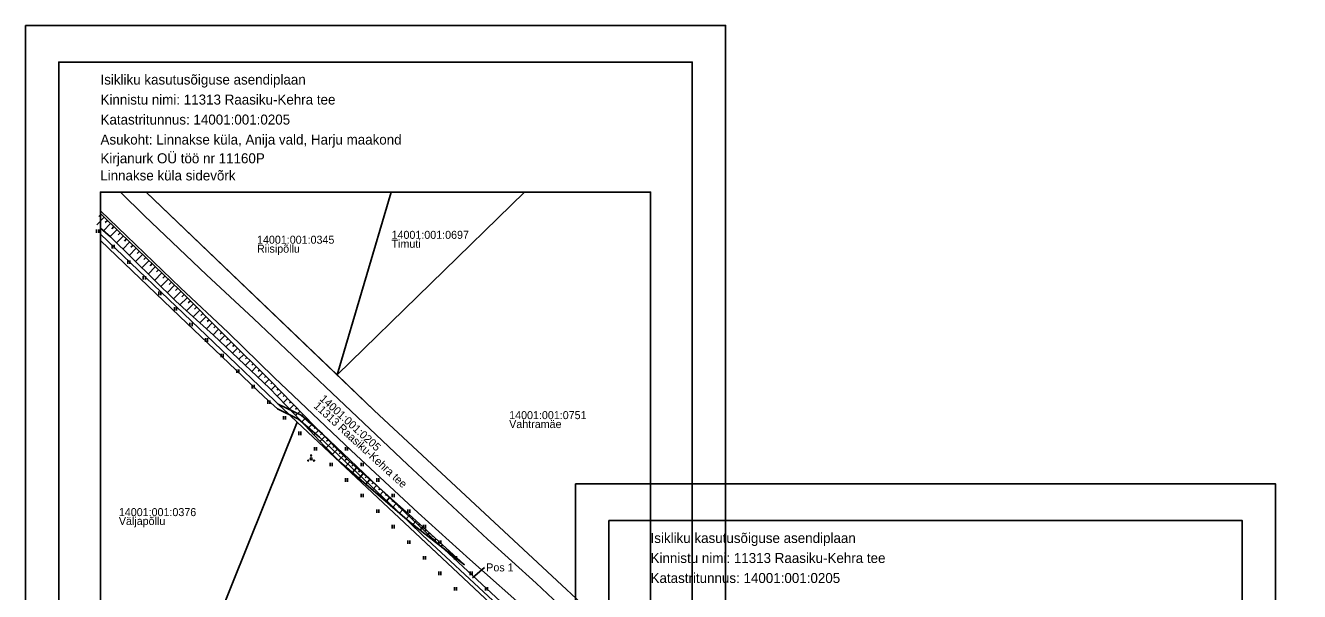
# Model space of a CAD drawing. Extents: x 567864 to 568657, y 6579839 to 6580994.
# Drawn here: x 567863.8 to 568150.4, y 6580866.9 to 6580994.3 of the extents above; entities that cross this region are included whole.
import ezdxf

# ---------------------------------------------------------------- set-up
doc = ezdxf.new("R2010")
doc.units = 0
for name, color, linetype in [('HALJASTUS', 7, 'Continuous'), ('KASUTUSALA', 7, 'Continuous'), ('PIIR', 7, 'Continuous'), ('PR_SIDE', 7, 'Continuous'), ('PUU', 7, 'Continuous'), ('RELJEEF', 7, 'Continuous'), ('TEE', 7, 'Continuous'), ('VORMISTUS', 7, 'Continuous'), ('VORMISTUS_1', 7, 'Continuous')]:
    doc.layers.add(name, color=color, linetype=linetype)

msp = doc.modelspace()

# ---------------------------------------------------------------- linework, layer by layer
at = {"layer": 'HALJASTUS'}
for p, q in [((567879.77, 6580948.38), (567879.77, 6580947.62)), ((567880.23, 6580948.38), (567880.23, 6580947.62)), ((567883.27, 6580944.88), (567883.27, 6580944.12)), ((567883.73, 6580944.88), (567883.73, 6580944.12)), ((567886.77, 6580941.38), (567886.77, 6580940.62)), ((567887.23, 6580941.38), (567887.23, 6580940.62)), ((567890.27, 6580937.88), (567890.27, 6580937.12)), ((567890.73, 6580937.88), (567890.73, 6580937.12)), ((567893.77, 6580934.38), (567893.77, 6580933.62)), ((567894.23, 6580934.38), (567894.23, 6580933.62)), ((567897.27, 6580930.88), (567897.27, 6580930.12)), ((567897.73, 6580930.88), (567897.73, 6580930.12)), ((567900.77, 6580927.38), (567900.77, 6580926.62)), ((567901.23, 6580927.38), (567901.23, 6580926.62)), ((567904.27, 6580923.88), (567904.27, 6580923.12)), ((567904.73, 6580923.88), (567904.73, 6580923.12)), ((567907.77, 6580920.38), (567907.77, 6580919.62)), ((567908.23, 6580920.38), (567908.23, 6580919.62)), ((567911.27, 6580916.88), (567911.27, 6580916.12)), ((567911.73, 6580916.88), (567911.73, 6580916.12)), ((567914.77, 6580913.38), (567914.77, 6580912.62)), ((567915.23, 6580913.38), (567915.23, 6580912.62)), ((567918.27, 6580909.88), (567918.27, 6580909.12)), ((567918.73, 6580909.88), (567918.73, 6580909.12)), ((567921.77, 6580906.38), (567921.77, 6580905.62)), ((567922.23, 6580906.38), (567922.23, 6580905.62)), ((567925.27, 6580902.88), (567925.27, 6580902.12)), ((567925.73, 6580902.88), (567925.73, 6580902.12)), ((567928.77, 6580899.38), (567928.77, 6580898.62)), ((567929.23, 6580899.38), (567929.23, 6580898.62)), ((567935.77, 6580899.38), (567935.77, 6580898.62)), ((567936.23, 6580899.38), (567936.23, 6580898.62)), ((567932.27, 6580895.88), (567932.27, 6580895.12)), ((567932.73, 6580895.88), (567932.73, 6580895.12)), ((567939.27, 6580895.88), (567939.27, 6580895.12)), ((567939.73, 6580895.88), (567939.73, 6580895.12)), ((567935.77, 6580892.38), (567935.77, 6580891.62)), ((567936.23, 6580892.38), (567936.23, 6580891.62)), ((567942.77, 6580892.38), (567942.77, 6580891.62)), ((567943.23, 6580892.38), (567943.23, 6580891.62)), ((567939.27, 6580888.88), (567939.27, 6580888.12)), ((567939.73, 6580888.88), (567939.73, 6580888.12)), ((567946.27, 6580888.88), (567946.27, 6580888.12)), ((567946.73, 6580888.88), (567946.73, 6580888.12)), ((567942.77, 6580885.38), (567942.77, 6580884.62)), ((567943.23, 6580885.38), (567943.23, 6580884.62)), ((567949.77, 6580885.38), (567949.77, 6580884.62)), ((567950.23, 6580885.38), (567950.23, 6580884.62)), ((567946.27, 6580881.88), (567946.27, 6580881.12)), ((567946.73, 6580881.88), (567946.73, 6580881.12)), ((567953.27, 6580881.88), (567953.27, 6580881.12)), ((567953.73, 6580881.88), (567953.73, 6580881.12)), ((567949.77, 6580878.38), (567949.77, 6580877.62)), ((567950.23, 6580878.38), (567950.23, 6580877.62)), ((567956.77, 6580878.38), (567956.77, 6580877.62)), ((567957.23, 6580878.38), (567957.23, 6580877.62)), ((567953.27, 6580874.88), (567953.27, 6580874.12)), ((567953.73, 6580874.88), (567953.73, 6580874.12)), ((567960.27, 6580874.88), (567960.27, 6580874.12)), ((567960.73, 6580874.88), (567960.73, 6580874.12)), ((567956.77, 6580871.38), (567956.77, 6580870.62)), ((567957.23, 6580871.38), (567957.23, 6580870.62)), ((567963.77, 6580871.38), (567963.77, 6580870.62)), ((567964.23, 6580871.38), (567964.23, 6580870.62)), ((567960.27, 6580867.88), (567960.27, 6580867.12)), ((567960.73, 6580867.88), (567960.73, 6580867.12)), ((567967.27, 6580867.88), (567967.27, 6580867.12)), ((567967.73, 6580867.88), (567967.73, 6580867.12))]:
    msp.add_line(p, q, dxfattribs=at)
at = {"layer": 'KASUTUSALA'}
msp.add_lwpolyline([(567990.1, 6580843.82), (567924.86, 6580904.98), (567920.6, 6580909.06), (567925.75, 6580906.55), (567930.61, 6580902.35), (567950.76, 6580883.2), (567953.75, 6580880.34), (567985.43, 6580850.94), (568001.13, 6580836.37), (568041.89, 6580797.25), (568048.6, 6580791.44), (568058.21, 6580782.73), (568069.7, 6580771.98), (568086.44, 6580756.19), (568091.52, 6580748.73), (568085.32, 6580754.55)], close=True, dxfattribs=at)
at = {"layer": 'PIIR'}
for points in [[(567946.02, 6580956.76), (567933.86, 6580915.64), (567890.89, 6580956.76)], [(567890.89, 6580956.76), (567942.23, 6580907.63), (568029.89, 6580826)], [(568029.89, 6580826), (567942.23, 6580907.63), (567933.86, 6580915.64), (567976.06, 6580956.76)], [(567976.06, 6580956.76), (567933.86, 6580915.64), (567946.02, 6580956.76)], [(567880.63, 6580947.31), (567924.86, 6580904.98), (567880.51, 6580794.46)], [(568029.89, 6580806.52), (567924.86, 6580904.98), (567880.63, 6580947.31)], [(567880.51, 6580794.46), (567924.86, 6580904.98), (567990.1, 6580843.82), (567986.28, 6580839.8), (567978.11, 6580830.11), (567948.05, 6580794.46)]]:
    msp.add_lwpolyline(points, dxfattribs=at)
at = {"layer": 'PR_SIDE'}
msp.add_lwpolyline([(568155.31, 6580687.84), (568141.84, 6580700.36), (568139.04, 6580702.91), (568131.77, 6580709.69), (568120.52, 6580720.13), (568105.22, 6580734.44), (568093.13, 6580745.84), (568090.59, 6580748.32), (568085.67, 6580755.54), (568069.02, 6580771.25), (568057.54, 6580782), (568047.92, 6580790.72), (568041.21, 6580796.51), (568000.44, 6580835.65), (567984.75, 6580850.21), (567953.07, 6580879.61), (567950.07, 6580882.48), (567929.94, 6580901.61), (567925.2, 6580905.7), (567920.48, 6580908.01), (567917.42, 6580910.73), (567898.41, 6580928.89), (567880.63, 6580945.92)], dxfattribs=at)
at = {"layer": 'PUU'}
for centre, radius in [((567927.37, 6580896.37), 0.125), ((567928.02, 6580896.75), 0.25), ((567928.02, 6580897.5), 0.125), ((567928.67, 6580896.37), 0.125)]:
    msp.add_circle(centre, radius, dxfattribs=at)
at = {"layer": 'RELJEEF'}
for p, q in [((567881.48, 6580951.12), (567879.79, 6580949.38)), ((567880.77, 6580951.82), (567880.25, 6580951.28)), ((567882.92, 6580949.73), (567881.31, 6580948.07)), ((567882.2, 6580950.42), (567881.7, 6580949.91)), ((567884.35, 6580948.33), (567882.83, 6580946.76)), ((567883.63, 6580949.03), (567883.16, 6580948.54)), ((567885.79, 6580946.94), (567884.26, 6580945.35)), ((567885.07, 6580947.63), (567884.61, 6580947.16)), ((567887.23, 6580945.55), (567885.68, 6580943.95)), ((567886.51, 6580946.24), (567886.05, 6580945.77)), ((567888.67, 6580944.16), (567887.11, 6580942.54)), ((567887.95, 6580944.86), (567887.48, 6580944.37)), ((567890.11, 6580942.77), (567888.53, 6580941.14)), ((567889.39, 6580943.47), (567888.92, 6580942.98)), ((567891.55, 6580941.39), (567889.95, 6580939.73)), ((567890.83, 6580942.08), (567890.35, 6580941.59)), ((567892.99, 6580940), (567891.38, 6580938.33)), ((567892.27, 6580940.69), (567891.79, 6580940.19)), ((567894.43, 6580938.61), (567892.8, 6580936.92)), ((567893.71, 6580939.3), (567893.22, 6580938.8)), ((567895.86, 6580937.22), (567894.22, 6580935.52)), ((567895.15, 6580937.92), (567894.65, 6580937.41)), ((567897.3, 6580935.83), (567895.65, 6580934.11)), ((567896.58, 6580936.53), (567896.09, 6580936.01)), ((567898.74, 6580934.44), (567897.03, 6580932.74)), ((567898.02, 6580935.14), (567897.52, 6580934.62)), ((567900.15, 6580933.02), (567898.5, 6580931.38)), ((567899.45, 6580933.73), (567898.94, 6580933.23)), ((567901.56, 6580931.61), (567899.99, 6580930.04)), ((567900.86, 6580932.31), (567900.37, 6580931.83)), ((567902.97, 6580930.19), (567901.48, 6580928.7)), ((567902.27, 6580930.9), (567901.81, 6580930.44)), ((567904.38, 6580928.77), (567902.97, 6580927.36)), ((567903.68, 6580929.48), (567903.24, 6580929.04)), ((567905.79, 6580927.35), (567904.46, 6580926.02)), ((567905.09, 6580928.06), (567904.67, 6580927.65)), ((567907.2, 6580925.93), (567905.95, 6580924.68)), ((567906.5, 6580926.64), (567906.11, 6580926.25)), ((567908.61, 6580924.51), (567907.4, 6580923.31)), ((567907.91, 6580925.22), (567907.54, 6580924.86)), ((567909.32, 6580923.81), (567908.96, 6580923.45)), ((567910.03, 6580923.1), (567908.86, 6580921.93)), ((567911.44, 6580921.69), (567910.32, 6580920.56)), ((567910.73, 6580922.39), (567910.39, 6580922.05)), ((567912.15, 6580920.98), (567911.82, 6580920.65)), ((567912.86, 6580920.27), (567911.77, 6580919.19)), ((567914.27, 6580918.86), (567913.23, 6580917.82)), ((567913.57, 6580919.57), (567913.25, 6580919.25)), ((567914.98, 6580918.15), (567914.67, 6580917.85)), ((567915.69, 6580917.45), (567914.68, 6580916.44)), ((567916.4, 6580916.74), (567916.1, 6580916.45)), ((567917.1, 6580916.03), (567916.14, 6580915.07)), ((567917.81, 6580915.33), (567917.53, 6580915.04)), ((567918.52, 6580914.62), (567917.6, 6580913.7)), ((567919.22, 6580913.91), (567918.95, 6580913.64)), ((567919.92, 6580913.19), (567919.02, 6580912.31)), ((567920.62, 6580912.48), (567920.35, 6580912.21)), ((567921.32, 6580911.77), (567920.4, 6580910.87)), ((567922.02, 6580911.05), (567921.74, 6580910.78)), ((567922.72, 6580910.34), (567921.78, 6580909.42)), ((567923.42, 6580909.62), (567923.14, 6580909.34)), ((567924.12, 6580908.91), (567923.16, 6580907.97)), ((567924.82, 6580908.19), (567924.53, 6580907.91)), ((567925.52, 6580907.48), (567924.54, 6580906.52)), ((567926.22, 6580906.77), (567925.92, 6580906.47)), ((567926.92, 6580906.05), (567925.91, 6580905.07)), ((567928.32, 6580904.62), (567927.28, 6580903.61)), ((567927.62, 6580905.34), (567927.31, 6580905.04)), ((567929.02, 6580903.91), (567928.71, 6580903.6)), ((567929.72, 6580903.2), (567928.66, 6580902.15)), ((567931.12, 6580901.77), (567930.03, 6580900.7)), ((567930.42, 6580902.48), (567930.1, 6580902.17)), ((567931.83, 6580901.06), (567931.49, 6580900.73)), ((567932.53, 6580900.35), (567931.41, 6580899.25)), ((567933.93, 6580898.92), (567932.81, 6580897.82)), ((567933.23, 6580899.63), (567932.89, 6580899.3)), ((567934.63, 6580898.21), (567934.3, 6580897.88)), ((567935.33, 6580897.5), (567934.21, 6580896.39)), ((567936.04, 6580896.78), (567935.71, 6580896.46)), ((567936.75, 6580896.09), (567935.79, 6580895)), ((567937.5, 6580895.43), (567937.21, 6580895.1)), ((567938.25, 6580894.76), (567937.3, 6580893.69)), ((567939, 6580894.1), (567938.71, 6580893.78)), ((567939.74, 6580893.43), (567938.81, 6580892.39)), ((567940.49, 6580892.77), (567940.21, 6580892.46)), ((567941.24, 6580892.1), (567940.33, 6580891.08)), ((567941.99, 6580891.44), (567941.71, 6580891.13)), ((567942.73, 6580890.77), (567941.84, 6580889.77)), ((567943.48, 6580890.11), (567943.22, 6580889.81)), ((567944.23, 6580889.44), (567943.35, 6580888.46)), ((567944.97, 6580888.78), (567944.72, 6580888.49)), ((567945.72, 6580888.12), (567944.87, 6580887.15)), ((567946.47, 6580887.45), (567946.22, 6580887.17)), ((567947.22, 6580886.79), (567946.38, 6580885.85)), ((567947.96, 6580886.12), (567947.72, 6580885.84)), ((567948.71, 6580885.46), (567947.89, 6580884.54)), ((567949.46, 6580884.79), (567949.22, 6580884.52)), ((567950.21, 6580884.13), (567949.41, 6580883.23)), ((567950.95, 6580883.46), (567950.71, 6580883.2)), ((567951.69, 6580882.79), (567950.94, 6580881.97)), ((567952.43, 6580882.11), (567952.22, 6580881.88)), ((567953.17, 6580881.44), (567952.52, 6580880.73)), ((567953.91, 6580880.77), (567953.73, 6580880.57)), ((567954.64, 6580880.09), (567954.1, 6580879.5)), ((567955.38, 6580879.42), (567955.24, 6580879.26)), ((567956.12, 6580878.74), (567955.68, 6580878.26)), ((567956.86, 6580878.07), (567956.74, 6580877.94)), ((567957.6, 6580877.39), (567957.26, 6580877.02)), ((567958.34, 6580876.72), (567958.25, 6580876.63)), ((567959.08, 6580876.05), (567958.84, 6580875.79)), ((567959.81, 6580875.37), (567959.76, 6580875.31)), ((567960.55, 6580874.7), (567960.42, 6580874.55)), ((567961.29, 6580874.02), (567961.27, 6580874)), ((567962.03, 6580873.35), (567962, 6580873.31))]:
    msp.add_line(p, q, dxfattribs=at)
for points in [[(567880.63, 6580951.95), (567885.14, 6580947.57), (567898.59, 6580934.6), (567908.97, 6580924.16), (567918.79, 6580914.35), (567928.86, 6580904.07), (567936.46, 6580896.35), (567950.84, 6580883.56), (567962.49, 6580872.93)], [(567880.63, 6580948.65), (567882.88, 6580946.72), (567897.55, 6580932.23), (567906.05, 6580924.59), (567918.68, 6580912.68), (567924.26, 6580906.82), (567931.06, 6580899.6), (567934.44, 6580896.16), (567950.18, 6580882.56), (567962.49, 6580872.93)]]:
    msp.add_lwpolyline(points, dxfattribs=at)
at = {"layer": 'TEE'}
for points in [[(568029.89, 6580820.99), (568027.95, 6580822.81), (568011.54, 6580838.14), (567999.57, 6580849.28), (567987.61, 6580860.42), (567978.62, 6580868.78), (567967.71, 6580878.66), (567949.67, 6580895.49), (567932.77, 6580911.54), (567915.08, 6580928.31), (567904.47, 6580938.19), (567890.55, 6580951.42), (567885.1, 6580956.76)], [(568029.89, 6580813.41), (568027.68, 6580815.58), (568020.88, 6580821.92), (568017.62, 6580824.97), (568007.56, 6580834.35), (567991.19, 6580849.21), (567977.62, 6580861.82), (567963.7, 6580874.09), (567952.11, 6580884.63), (567937.05, 6580898.67), (567919.72, 6580915.09), (567909.39, 6580925.15), (567898.65, 6580935.27), (567886.52, 6580946.91), (567880.63, 6580952.55)]]:
    msp.add_lwpolyline(points, dxfattribs=at)
at = {"layer": 'VORMISTUS'}
msp.add_line((567964.33, 6580869.95), (567967.05, 6580872.33), dxfattribs=at)
for points in [[(567863.76, 6580994.26), (568021.26, 6580994.26), (568021.26, 6580771.51), (567863.76, 6580771.51)], [(567871.26, 6580779.76), (568013.76, 6580779.76), (568013.76, 6580986.01), (567871.26, 6580986.01)], [(567871.26, 6580986.01), (568013.76, 6580986.01), (568013.76, 6580779.76), (567871.26, 6580779.76)], [(568004.38, 6580799.26), (567880.63, 6580799.26), (567880.63, 6580956.76), (568004.38, 6580956.76)]]:
    msp.add_lwpolyline(points, close=True, dxfattribs=at)
at = {"layer": 'VORMISTUS_1'}
for points in [[(567987.51, 6580891.12), (568145.01, 6580891.12), (568145.01, 6580668.37), (567987.51, 6580668.37)], [(567995.01, 6580676.62), (568137.51, 6580676.62), (568137.51, 6580882.87), (567995.01, 6580882.87)], [(567995.01, 6580882.87), (568137.51, 6580882.87), (568137.51, 6580676.62), (567995.01, 6580676.62)]]:
    msp.add_lwpolyline(points, close=True, dxfattribs=at)

# ---------------------------------------------------------------- texts
at = {"layer": 'PIIR'}
for s, p in [('14001:001:0345', (567915.85, 6580945.16)), ('14001:001:0697', (567946.12, 6580946.26)), ('Riisipõllu', (567915.85, 6580943.15)), ('Timuti', (567946.12, 6580944.25)), ('14001:001:0751', (567972.58, 6580905.69)), ('Vahtramäe', (567972.58, 6580903.68)), ('Väljapõllu', (567884.77, 6580881.87)), ('14001:001:0376', (567884.77, 6580883.87))]:
    msp.add_text(s, height=1.8, dxfattribs=at).set_placement(p)
for s, p in [('14001:001:0205', (567929.82, 6580910.06)), ('11313 Raasiku-Kehra tee', (567928.45, 6580908.45))]:
    msp.add_text(s, height=1.8, rotation=317.6446, dxfattribs=at).set_placement(p)
at = {"layer": 'VORMISTUS'}
for s, height, p in [('Isikliku kasutusõiguse asendiplaan', 2.25, (567880.64, 6580980.97)), ('Kinnistu nimi: 11313 Raasiku-Kehra tee', 2.25, (567880.64, 6580976.47)), ('Katastritunnus: 14001:001:0205', 2.25, (567880.64, 6580971.97)), ('Asukoht: Linnakse küla, Anija vald, Harju maakond', 2.25, (567880.64, 6580967.47)), ('Pos 1', 1.8, (567967.42, 6580871.43))]:
    msp.add_text(s, height=height, dxfattribs=at).set_placement(p)
for s, p in [('Kirjanurk OÜ töö nr 11160P', (567880.63, 6580963.26)), ('Linnakse küla sidevõrk', (567880.57, 6580959.4))]:
    msp.add_text(s, height=2.25, rotation=360, dxfattribs=at).set_placement(p)
at = {"layer": 'VORMISTUS_1'}
for s, p in [('Isikliku kasutusõiguse asendiplaan', (568004.39, 6580877.82)), ('Kinnistu nimi: 11313 Raasiku-Kehra tee', (568004.39, 6580873.32)), ('Katastritunnus: 14001:001:0205', (568004.39, 6580868.82))]:
    msp.add_text(s, height=2.25, dxfattribs=at).set_placement(p)

doc.saveas('drawing.dxf')
